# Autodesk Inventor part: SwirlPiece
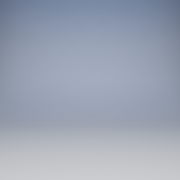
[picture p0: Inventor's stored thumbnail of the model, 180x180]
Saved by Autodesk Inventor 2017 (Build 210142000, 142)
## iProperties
Created: 2017-05
Part Number: SwirlPiece
Material: Generic
Document SubType Name: Modeling
Designer: 1460374
Density: 1 g/cm^3
Appearance: Default
Author: 1460374
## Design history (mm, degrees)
sketch "Sketch1"
  geometry: L1 (85.079, 88.815)-(85.079, 71.815) reference; L2 (85.079, 86.665)-(85.079, 86.065); L3 (85.079, 74.565)-(85.079, 73.965); L4 (85.079, 86.065)-(85.079, 74.565); A1 r 6.35 centre (85.079, 80.315) between (86.898, 86.399) and (86.898, 74.231) reference; A2 r 6.35 centre (85.079, 80.315) between (85.079, 86.665) and (85.079, 73.965); A3 r 5.75 centre (85.079, 80.315) between (85.079, 86.065) and (85.079, 74.565); 1 further point
  constraints: 6 end point, 4 point on circle, 2 centre point, 2 point on line, 1 coincident, 1 collinear, 1 concentric
  dimensions: "d0" = 0.6 radial gap between concentric circles of A1 A3
  node "Reference1"
  node "Reference2"
workplane "Work Plane1"
extrude "Extrusion1" new body sketch "Sketch1" stored distance "d1" = 10; taper "d2" = 0 deg
feature "FaceDraft1" dims angle "d3" = -15 deg
body "Solid1"
